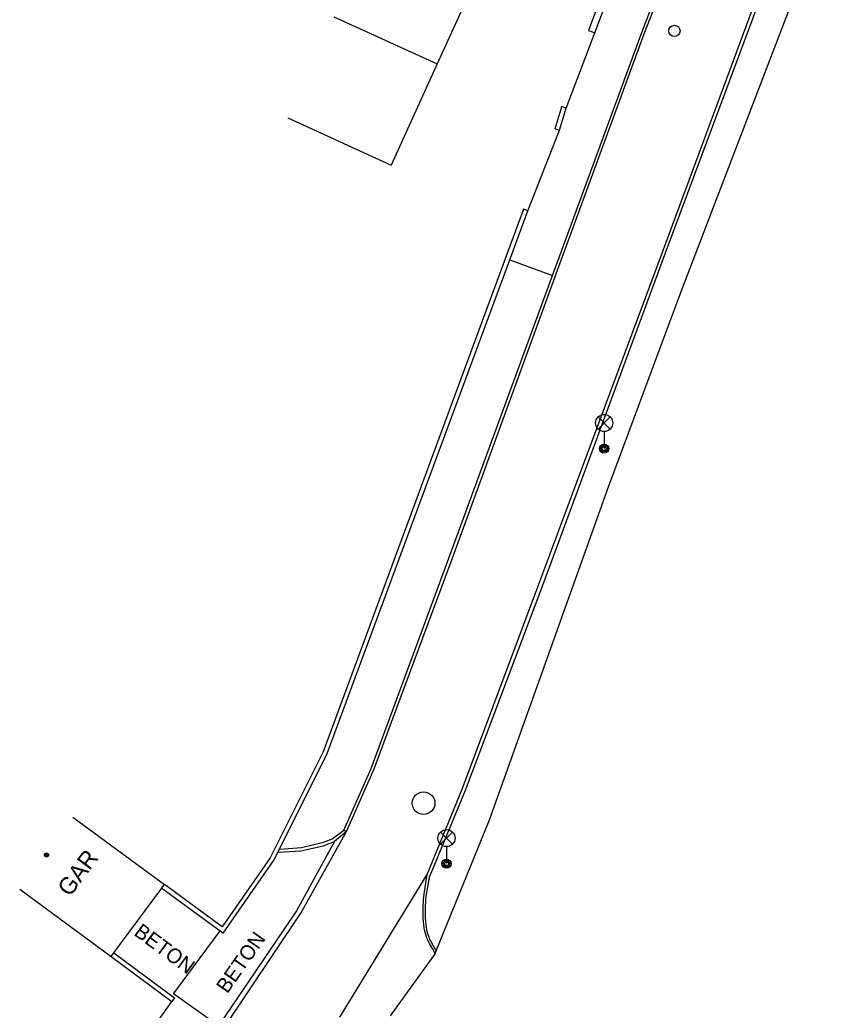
# Model space of a CAD drawing. Extents: x -538441 to -536770, y -1181008 to -1179809.
# Drawn here: x -537579.47 to -537543.58, y -1180585.46 to -1180541.89 of the extents above; entities that cross this region are included whole.
import ezdxf

# ---------------------------------------------------------------- set-up
doc = ezdxf.new("R2010")
doc.units = 0
for name, color, linetype in [('Vrstva 10', 7, 'Continuous'), ('Vrstva 11', 7, 'Continuous'), ('Vrstva 27', 7, 'Continuous'), ('Vrstva 28', 7, 'Continuous'), ('Vrstva 33', 7, 'Continuous'), ('Vrstva 39', 7, 'Continuous'), ('Vrstva 40', 7, 'Continuous'), ('Vrstva 41', 7, 'Continuous'), ('Vrstva 5', 7, 'Continuous'), ('Vrstva 7', 7, 'Continuous'), ('Vrstva 8', 7, 'Continuous')]:
    doc.layers.add(name, color=color, linetype=linetype)

msp = doc.modelspace()

# ---------------------------------------------------------------- linework, layer by layer
at = {"layer": 'Vrstva 10'}
for p, q in [((-537552.04, -1180542.63), (-537547.93, -1180531.88)), ((-537551.18, -1180552.11), (-537545.21, -1180536.01)), ((-537555.86, -1180553.07), (-537552.04, -1180542.63)), ((-537556.62, -1180566.72), (-537551.18, -1180552.11)), ((-537560.36, -1180565.36), (-537555.86, -1180553.07)), ((-537563.87, -1180574.84), (-537560.36, -1180565.36)), ((-537560, -1180575.73), (-537556.62, -1180566.72)), ((-537561.54, -1180579.49), (-537560, -1180575.73)), ((-537565.39, -1180585.76), (-537561.54, -1180579.49)), ((-537570.52, -1180586.29), (-537567.1, -1180581.19))]:
    msp.add_line(p, q, dxfattribs=at)
for points in [[(-537567.1, -1180581.19), (-537565.09, -1180577.6), (-537563.87, -1180574.84)], [(-537561.19, -1180582.96), (-537561.313, -1180582.744), (-537561.436, -1180582.528), (-537561.475, -1180582.455), (-537561.509, -1180582.384), (-537561.537, -1180582.317), (-537561.562, -1180582.253), (-537561.602, -1180582.129), (-537561.631, -1180582.019), (-537561.653, -1180581.922), (-537561.669, -1180581.835), (-537561.691, -1180581.683), (-537561.703, -1180581.569), (-537561.715, -1180581.398), (-537561.72, -1180581.23), (-537561.72, -1180581.031), (-537561.716, -1180580.856), (-537561.707, -1180580.702), (-537561.696, -1180580.567), (-537561.682, -1180580.449), (-537561.668, -1180580.346), (-537561.654, -1180580.256), (-537561.54, -1180579.49)]]:
    msp.add_lwpolyline(points, dxfattribs=at)
at = {"layer": 'Vrstva 11'}
for p, q in [((-537552.14, -1180542.56), (-537548.06, -1180531.85)), ((-537545.07, -1180536.09), (-537551.06, -1180552.15)), ((-537555.98, -1180553.02), (-537552.14, -1180542.56)), ((-537551.06, -1180552.15), (-537556.47, -1180566.78)), ((-537557.908, -1180552.449), (-537556.026, -1180553.145)), ((-537564, -1180574.83), (-537560.48, -1180565.3)), ((-537556.47, -1180566.78), (-537559.87, -1180575.8)), ((-537565.21, -1180577.54), (-537564, -1180574.83)), ((-537559.87, -1180575.8), (-537561.43, -1180579.55)), ((-537567.3, -1180581.08), (-537570.72, -1180586.14))]:
    msp.add_line(p, q, dxfattribs=at)
for points in [[(-537556.026, -1180553.145), (-537555.98, -1180553.02)], [(-537560.48, -1180565.3), (-537556.026, -1180553.145)], [(-537565.72, -1180577.92), (-537565.21, -1180577.54), (-537565.09, -1180577.6), (-537565.62, -1180578.04), (-537567.3, -1180581.08)], [(-537568.11, -1180578.51), (-537567.106, -1180578.447), (-537566.124, -1180578.222), (-537565.62, -1180578.04)], [(-537568.04, -1180578.37), (-537567.08, -1180578.3), (-537566.108, -1180578.064), (-537565.72, -1180577.92)], [(-537561.142, -1180582.843), (-537561.348, -1180582.48), (-537561.386, -1180582.41), (-537561.418, -1180582.343), (-537561.444, -1180582.28), (-537561.468, -1180582.219), (-537561.506, -1180582.101), (-537561.534, -1180581.995), (-537561.555, -1180581.902), (-537561.57, -1180581.819), (-537561.592, -1180581.671), (-537561.603, -1180581.56), (-537561.615, -1180581.393), (-537561.62, -1180581.229), (-537561.62, -1180581.032), (-537561.616, -1180580.86), (-537561.607, -1180580.709), (-537561.596, -1180580.577), (-537561.583, -1180580.462), (-537561.569, -1180580.36), (-537561.555, -1180580.273), (-537561.526, -1180580.121), (-537561.43, -1180579.55)], [(-537570.72, -1180586.14), (-537572.71, -1180584.74), (-537570.658, -1180581.969)]]:
    msp.add_lwpolyline(points, dxfattribs=at)
at = {"layer": 'Vrstva 27'}
msp.add_circle((-537561.7, -1180576.35), 0.5, dxfattribs=at)
at = {"layer": 'Vrstva 28'}
msp.add_circle((-537550.66, -1180542.38), 0.25, dxfattribs=at)
at = {"layer": 'Vrstva 33'}
for p, q in [((-537554.014, -1180559.891), (-537553.486, -1180559.361)), ((-537554.014, -1180559.361), (-537553.486, -1180559.891)), ((-537553.75, -1180560), (-537553.75, -1180560.75)), ((-537560.954, -1180578.151), (-537560.426, -1180577.621)), ((-537560.954, -1180577.621), (-537560.426, -1180578.151)), ((-537560.69, -1180578.26), (-537560.69, -1180579.01))]:
    msp.add_line(p, q, dxfattribs=at)
for centre, radius in [((-537553.75, -1180559.626), 0.375), ((-537553.75, -1180560.751), 0.2), ((-537553.75, -1180560.751), 0.145), ((-537553.75, -1180560.751), 0.0876), ((-537560.69, -1180577.886), 0.375), ((-537560.69, -1180579.011), 0.2), ((-537560.69, -1180579.011), 0.145), ((-537560.69, -1180579.011), 0.0876)]:
    msp.add_circle(centre, radius, dxfattribs=at)
at = {"layer": 'Vrstva 39'}
for radius in [0.09, 0.0398]:
    msp.add_circle((-537578.298, -1180578.629), radius, dxfattribs=at)
at = {"layer": 'Vrstva 5'}
for p, q in [((-537557.829, -1180536.63), (-537561.1, -1180543.83)), ((-537565.652, -1180541.762), (-537561.1, -1180543.83)), ((-537561.1, -1180543.83), (-537563.13, -1180548.28)), ((-537567.679, -1180546.205), (-537563.13, -1180548.28)), ((-537577.133, -1180576.961), (-537573.11, -1180579.93)), ((-537573.228, -1180580.09), (-537573.11, -1180579.93)), ((-537579.473, -1180580.131), (-537575.45, -1180583.1)), ((-537575.331, -1180582.939), (-537573.228, -1180580.09)), ((-537575.45, -1180583.1), (-537575.331, -1180582.939))]:
    msp.add_line(p, q, dxfattribs=at)
at = {"layer": 'Vrstva 7'}
for p, q in [((-537551.065, -1180533.39), (-537554.441, -1180542.364)), ((-537550.4, -1180553.96), (-537543.58, -1180536.14)), ((-537555.911, -1180546.691), (-537555.611, -1180545.711)), ((-537557.298, -1180550.221), (-537566.124, -1180574.09)), ((-537565.94, -1180574.17), (-537557.908, -1180552.449)), ((-537553.56, -1180562.44), (-537550.4, -1180553.96)), ((-537558.8, -1180577.08), (-537553.56, -1180562.44)), ((-537566.124, -1180574.09), (-537568.452, -1180578.748)), ((-537575.45, -1180583.1), (-537572.779, -1180585.071))]:
    msp.add_line(p, q, dxfattribs=at)
for points in [[(-537554.16, -1180542.47), (-537550.68, -1180533.22)], [(-537554.441, -1180542.364), (-537554.16, -1180542.47)], [(-537555.911, -1180546.691), (-537555.72, -1180546.75), (-537555.42, -1180545.77), (-537555.611, -1180545.711)], [(-537557.908, -1180552.449), (-537557.11, -1180550.29), (-537557.298, -1180550.221)], [(-537568.28, -1180578.85), (-537568.11, -1180578.51), (-537568.04, -1180578.37), (-537565.94, -1180574.17)], [(-537561.142, -1180582.843), (-537558.8, -1180577.08)], [(-537568.452, -1180578.748), (-537570.567, -1180581.788), (-537573.11, -1180579.93)], [(-537573.228, -1180580.09), (-537570.658, -1180581.969), (-537570.52, -1180582.07), (-537568.28, -1180578.85)], [(-537575.331, -1180582.939), (-537572.66, -1180584.91), (-537572.779, -1180585.071)], [(-537561.19, -1180582.96), (-537561.142, -1180582.843)]]:
    msp.add_lwpolyline(points, dxfattribs=at)
at = {"layer": 'Vrstva 8'}
for p, q in [((-537555.42, -1180545.77), (-537554.16, -1180542.47)), ((-537557.11, -1180550.29), (-537555.72, -1180546.75)), ((-537561.19, -1180582.96), (-537563.17, -1180585.7)), ((-537573.46, -1180586.03), (-537572.779, -1180585.071))]:
    msp.add_line(p, q, dxfattribs=at)

# ---------------------------------------------------------------- texts
at = {"layer": 'Vrstva 40'}
for rotation, p in [(323.5754, (-537574.491, -1180582.123)), (54.9456, (-537570.339, -1180584.759))]:
    msp.add_text('BETON', height=0.65, rotation=rotation, dxfattribs=at).set_placement(p)
at = {"layer": 'Vrstva 41'}
msp.add_text('GAR', height=0.75, rotation=53.5664, dxfattribs=at).set_placement((-537577.264, -1180580.505))

doc.saveas('drawing.dxf')
